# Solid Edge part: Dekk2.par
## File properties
Author: Egon 815
Template: Normal.par
Last saved by: Egon 815
Revision: 5
Application: Solid Edge
Accuracy: 0,990
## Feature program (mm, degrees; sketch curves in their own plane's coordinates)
sketch for "unnamed Protrusion 1" plane through (0, 0, 7184.8312) normal (0, 0, 1) x-axis (1, 0, 0)
  line (5785.9629, -45561.1482) -> (8447.4206, -42019.6798)
  line (8447.4206, -42019.6798) -> (8447.4206, -28321.7499)
  line (8447.4206, -28321.7499) -> (10085.7112, -23270.3538)
  line (10085.7112, -23270.3538) -> (9312.0739, -21267.9986)
  line (9312.0739, -21267.9986) -> (10586.3, -15124.4087)
  line (10586.3, -15124.4087) -> (9312.0739, -11802.3194)
  line (9312.0739, -11802.3194) -> (10586.3, -8889.8027)
  line (10586.3, -8889.8027) -> (9312.0739, -5021.6165)
  line (9312.0739, -5021.6165) -> (0, -5021.6165)
  line (-9312.0739, -5021.6165) -> (0, -5021.6165)
  line (-10586.3, -8889.8027) -> (-9312.0739, -5021.6165)
  line (-9312.0739, -11802.3194) -> (-10586.3, -8889.8027)
  line (-10586.3, -15124.4087) -> (-9312.0739, -11802.3194)
  line (-9312.0739, -21267.9986) -> (-10586.3, -15124.4087)
  line (-10085.7112, -23270.3538) -> (-9312.0739, -21267.9986)
  line (-8447.4206, -28321.7499) -> (-10085.7112, -23270.3538)
  line (-8447.4206, -42019.6798) -> (-8447.4206, -28321.7499)
  line (-5785.9629, -45561.1482) -> (-8447.4206, -42019.6798)
  line (-5785.9629, -45561.1482) -> (-5785.9629, -50835.3127)
  line (-5785.9629, -50835.3127) -> (-4382.7449, -53593.3621)
  line (-4382.7449, -53593.3621) -> (0, -53593.3621)
  line (4382.7449, -53593.3621) -> (0, -53593.3621)
  line (5785.9629, -50835.3127) -> (4382.7449, -53593.3621)
  line (5785.9629, -45561.1482) -> (5785.9629, -50835.3127)
extrude "unnamed Protrusion 1" add to key point along +normal
logasc func "Lip_Groove_1"  LipOrGrooveWidth = 60 mm; LipOrGrooveHeight = 1000 mm
sketch for "ExtrudedCutout_1" #1 plane through (0, 0, 0) normal (1, 0, 0) x-axis (0, 1, 0)
  line (-52885.4955, 11063.589) -> (-52885.4955, 10563.589)
  line (-52885.4955, 10563.589) -> (-51885.4955, 10563.589)
  line (-51885.4955, 10563.589) -> (-51885.4955, 11063.589)
  line (-51885.4955, 11063.589) -> (-52885.4955, 11063.589)
sketch for "ExtrudedCutout_1" #2 plane through (0, 0, 0) normal (1, 0, 0) x-axis (0, 1, 0)
  line (-45061.1482, 11063.589) -> (-46061.1482, 11063.589)
  line (-46061.1482, 11063.589) -> (-46061.1482, 10563.589)
  line (-46061.1482, 10563.589) -> (-45061.1482, 10563.589)
  line (-45061.1482, 10563.589) -> (-45061.1482, 11063.589)
sketch for "ExtrudedCutout_1" #3 plane through (0, 0, 0) normal (1, 0, 0) x-axis (0, 1, 0)
  line (-38761.9514, 11063.589) -> (-38761.9514, 10563.589)
  line (-38761.9514, 10563.589) -> (-37761.9514, 10563.589)
  line (-37761.9514, 10563.589) -> (-37761.9514, 11063.589)
  line (-37761.9514, 11063.589) -> (-38761.9514, 11063.589)
sketch for "ExtrudedCutout_1" #4 plane through (0, 0, 0) normal (1, 0, 0) x-axis (0, 1, 0)
  line (-32320.3539, 11063.589) -> (-33320.3539, 11063.589)
  line (-33320.3539, 11063.589) -> (-33320.3539, 10563.589)
  line (-33320.3539, 10563.589) -> (-32320.3539, 10563.589)
  line (-32320.3539, 10563.589) -> (-32320.3539, 11063.589)
sketch for "ExtrudedCutout_1" #5 plane through (0, 0, 0) normal (1, 0, 0) x-axis (0, 1, 0)
  line (-22770.3538, 11063.589) -> (-23770.3538, 11063.589)
  line (-23770.3538, 11063.589) -> (-23770.3538, 10563.589)
  line (-23770.3538, 10563.589) -> (-22770.3538, 10563.589)
  line (-22770.3538, 10563.589) -> (-22770.3538, 11063.589)
sketch for "ExtrudedCutout_1" #6 plane through (0, 0, 0) normal (1, 0, 0) x-axis (0, 1, 0)
  line (-14624.4087, 11063.589) -> (-15624.4087, 11063.589)
  line (-15624.4087, 11063.589) -> (-15624.4087, 10563.589)
  line (-15624.4087, 10563.589) -> (-14624.4087, 10563.589)
  line (-14624.4087, 10563.589) -> (-14624.4087, 11063.589)
sketch for "ExtrudedCutout_1" #7 plane through (0, 0, 0) normal (1, 0, 0) x-axis (0, 1, 0)
  line (-8389.8027, 11063.589) -> (-9389.8027, 11063.589)
  line (-9389.8027, 11063.589) -> (-9389.8027, 10563.589)
  line (-9389.8027, 10563.589) -> (-8389.8027, 10563.589)
  line (-8389.8027, 10563.589) -> (-8389.8027, 11063.589)
extrude "ExtrudedCutout_1" cut finite symmetric
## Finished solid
Body 1: solid body, 89 faces, 324 edges, 216 vertices.
  Faces by surface: plane 89
  Edges by curve: line 324
Bounding box of the edges (mm): 21172.600 x 48571.745 x 4378.758, from (-10586.3, -53593.3621, 7184.8312) to (10586.3, -5021.6165, 11563.589).
Planar faces by outward normal: +x 4, +y 16, +z 2, -x 4, -y 16, -z 15, oblique 32
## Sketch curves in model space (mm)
line (0, -51885.4955, 11063.589) -> (0, -52885.4955, 11063.589)
line (0, -52885.4955, 11063.589) -> (0, -52885.4955, 10563.589)
line (0, -52885.4955, 10563.589) -> (0, -51885.4955, 10563.589)
line (0, -51885.4955, 10563.589) -> (0, -51885.4955, 11063.589)
line (0, -14624.4087, 11063.589) -> (0, -15624.4087, 11063.589)
line (0, -15624.4087, 11063.589) -> (0, -15624.4087, 10563.589)
line (0, -15624.4087, 10563.589) -> (0, -14624.4087, 10563.589)
line (0, -14624.4087, 10563.589) -> (0, -14624.4087, 11063.589)
line (0, -8389.8027, 11063.589) -> (0, -9389.8027, 11063.589)
line (0, -9389.8027, 11063.589) -> (0, -9389.8027, 10563.589)
line (0, -9389.8027, 10563.589) -> (0, -8389.8027, 10563.589)
line (0, -8389.8027, 10563.589) -> (0, -8389.8027, 11063.589)
line (0, -22770.3538, 11063.589) -> (0, -23770.3538, 11063.589)
line (0, -23770.3538, 11063.589) -> (0, -23770.3538, 10563.589)
line (0, -23770.3538, 10563.589) -> (0, -22770.3538, 10563.589)
line (0, -22770.3538, 10563.589) -> (0, -22770.3538, 11063.589)
line (0, -45061.1482, 11063.589) -> (0, -46061.1482, 11063.589)
line (0, -46061.1482, 11063.589) -> (0, -46061.1482, 10563.589)
line (0, -46061.1482, 10563.589) -> (0, -45061.1482, 10563.589)
line (0, -45061.1482, 10563.589) -> (0, -45061.1482, 11063.589)
line (0, -37761.9514, 11063.589) -> (0, -38761.9514, 11063.589)
line (0, -38761.9514, 11063.589) -> (0, -38761.9514, 10563.589)
line (0, -38761.9514, 10563.589) -> (0, -37761.9514, 10563.589)
line (0, -37761.9514, 10563.589) -> (0, -37761.9514, 11063.589)
line (0, -32320.3539, 11063.589) -> (0, -33320.3539, 11063.589)
line (0, -33320.3539, 11063.589) -> (0, -33320.3539, 10563.589)
line (0, -33320.3539, 10563.589) -> (0, -32320.3539, 10563.589)
line (0, -32320.3539, 10563.589) -> (0, -32320.3539, 11063.589)
line (0, -5021.6165, 7184.8312) -> (0, -5021.6165, 10563.589)
line (0, -42546.9286, 10563.589) -> (0, -5021.6165, 10563.589)
line (0, -42546.9286, 10563.589) -> (0, -53593.3621, 10563.589)
line (0, -53593.3621, 7184.8312) -> (0, -53593.3621, 10563.589)
line (5785.9629, -50835.3127, 7184.8312) -> (4382.7449, -53593.3621, 7184.8312)
line (4382.7449, -53593.3621, 7184.8312) -> (0, -53593.3621, 7184.8312)
line (-4382.7449, -53593.3621, 7184.8312) -> (0, -53593.3621, 7184.8312)
line (-5785.9629, -50835.3127, 7184.8312) -> (-4382.7449, -53593.3621, 7184.8312)
line (-5785.9629, -45561.1482, 7184.8312) -> (-5785.9629, -50835.3127, 7184.8312)
line (-5785.9629, -45561.1482, 7184.8312) -> (-8447.4206, -42019.6798, 7184.8312)
line (-8447.4206, -42019.6798, 7184.8312) -> (-8447.4206, -28321.7499, 7184.8312)
line (-8447.4206, -28321.7499, 7184.8312) -> (-10085.7112, -23270.3538, 7184.8312)
line (-10085.7112, -23270.3538, 7184.8312) -> (-9312.0739, -21267.9986, 7184.8312)
line (-9312.0739, -21267.9986, 7184.8312) -> (-10586.3, -15124.4087, 7184.8312)
line (-10586.3, -15124.4087, 7184.8312) -> (-9312.0739, -11802.3194, 7184.8312)
line (-9312.0739, -11802.3194, 7184.8312) -> (-10586.3, -8889.8027, 7184.8312)
line (-10586.3, -8889.8027, 7184.8312) -> (-9312.0739, -5021.6165, 7184.8312)
line (-9312.0739, -5021.6165, 7184.8312) -> (0, -5021.6165, 7184.8312)
line (9312.0739, -5021.6165, 7184.8312) -> (0, -5021.6165, 7184.8312)
line (10586.3, -8889.8027, 7184.8312) -> (9312.0739, -5021.6165, 7184.8312)
line (9312.0739, -11802.3194, 7184.8312) -> (10586.3, -8889.8027, 7184.8312)
line (10586.3, -15124.4087, 7184.8312) -> (9312.0739, -11802.3194, 7184.8312)
line (9312.0739, -21267.9986, 7184.8312) -> (10586.3, -15124.4087, 7184.8312)
line (10085.7112, -23270.3538, 7184.8312) -> (9312.0739, -21267.9986, 7184.8312)
line (8447.4206, -28321.7499, 7184.8312) -> (10085.7112, -23270.3538, 7184.8312)
line (8447.4206, -42019.6798, 7184.8312) -> (8447.4206, -28321.7499, 7184.8312)
line (5785.9629, -45561.1482, 7184.8312) -> (8447.4206, -42019.6798, 7184.8312)
line (5785.9629, -45561.1482, 7184.8312) -> (5785.9629, -50835.3127, 7184.8312)
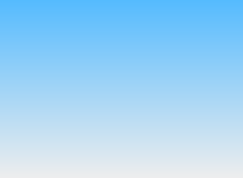
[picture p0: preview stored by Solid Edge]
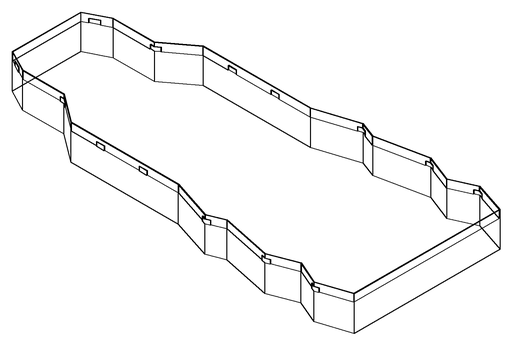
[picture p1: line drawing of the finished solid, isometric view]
